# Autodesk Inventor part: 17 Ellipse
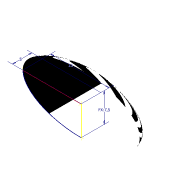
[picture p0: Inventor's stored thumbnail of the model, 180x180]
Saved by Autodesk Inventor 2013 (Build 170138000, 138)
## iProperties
Created: 2012-10
Part Number: 17 Ellipse
Material: Allgemein
Vendor: www.inventor-faq.de
Document SubType Name: Modeling
Designer: Administrator
Manufacturer: www.inventor-faq.de
Density: 1 g/cm^3
RuleStatus: InUse
AfterDocOpen0: inventorfaq
BeforeDocSave0: inventorfaq
Author: Administrator
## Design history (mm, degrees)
sketch "Skizze1" dims "d0" = 5, "d2" = 15
  geometry: L1 (-15, 0)-(0, 0); L2 (0, 0)-(0, 5); 1 further point; 1 other entity
  constraints: 4 end point, 1 coincident, 1 horizontal, 1 vertical, 4 other
sketch "Skizze2" dims "d3" = 7.5 (= 0.5 x d2)
  geometry: L1 (0, 0)-(0, -7.5); L2 (0, 0)-(5, 0); 2 further points; 1 other entity
  constraints: 4 end point, 1 coincident, 1 perpendicular, 1 vertical, 4 other
sketch "Skizze3"
  geometry: L1 (0, 0)-(0, -7.5); L2 (0, 0)-(15, 0); 1 further point; 1 other entity
  constraints: 4 end point, 1 coincident, 1 horizontal, 1 vertical, 4 other
feature "Extrusionsfläche1" dims "d11" = 2, "d12" = 0
feature "Extrusionsfläche2" dims "d13" = 2, "d14" = 0
feature "Formen1"
mirror "Spiegeln3"
mirror "Spiegeln4"
node "Volumenkörper2"
node "Fläche1"
node "Fläche2"
node "Kanten1"
node "Kanten2"
node "Fläche3"
feature "Erhabene Fläche1" dims "d15" = 10, "d16" = 90 deg, "d17" = 10, "d18" = 90 deg, "d19" = 0, "d20" = 90 deg
